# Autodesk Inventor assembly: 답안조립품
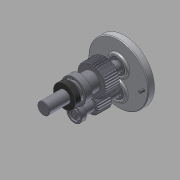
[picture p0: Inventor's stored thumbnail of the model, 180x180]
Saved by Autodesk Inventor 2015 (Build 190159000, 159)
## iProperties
Created: 2016-02
Part Number: 답안조립품
Document SubType Name: Assembly
Designer: Administrator
Author: Administrator
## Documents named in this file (10)
- C:\Users\Administrator\Desktop\460209V1002\답안조립품.iam
- C:\Users\Administrator\Desktop\460209V1002\본체.ipt
- C:\Users\Administrator\Desktop\460209V1002\오일실 17 32 8.ipt
- C:\Users\Administrator\Desktop\460209V1002\베어링 6003.ipt
- C:\Users\Administrator\Desktop\460209V1002\베어링 608.ipt
- C:\Users\Administrator\Desktop\460209V1002\서브축.ipt
- C:\Users\Administrator\Desktop\460209V1002\커버.ipt
- C:\Users\Administrator\Desktop\460209V1002\오일실 8 22 7.ipt
- C:\Users\Administrator\Desktop\460209V1002\볼트 M4 x 10.ipt
- C:\Users\Administrator\Desktop\460209V1002\메인축.ipt
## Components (2 placed, 1 different names)
1. ISO 4762 M4 x 10:1 — Insert:1
2. ISO 4762 M4 x 10:2 — Insert:2
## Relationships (2: Insert 2)
- Insert:1: ISO 4762 M4 x 10:1
- Insert:2: ISO 4762 M4 x 10:2
